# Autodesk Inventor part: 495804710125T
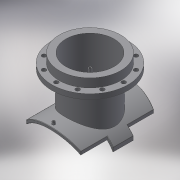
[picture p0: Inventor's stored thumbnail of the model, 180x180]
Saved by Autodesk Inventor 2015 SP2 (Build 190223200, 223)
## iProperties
Created: 2017-10
Part Number: 495804710125T
Material: Generic
Description: PLASSON FLANGED BRANCH SADDLE 315-400X250
Document SubType Name: Modeling
Designer: KIM
Density: 1 g/cm^3
Appearance: Default
Author: KIM
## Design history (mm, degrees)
derived "495904.ipt"
feature "Solid1::495904.ipt"
feature "Solid2::495904.ipt"
tag "TaggingFeature1"
body "Solid1"
other parameters: "d1" = 15, "d2" = 283.5, "d4" = 0, "d5" = 315, "d6" = 105, "d7" = 0, "d11" = 2, "d12" = 225.6, "d13" = 14, "d14" = 189, "d16" = 5 deg, "d18" = 4, "d19" = 14, "d20" = 0, "d21" = 3, "d22" = 0, "d36" = 189, "d38" = 0, "d39" = 2, "d40" = 225, "d43" = 395, "d46" = 256, "d47" = 16, "d48" = 10.4, "d49" = 157.5, "d51" = 408, "d53" = 0, "d54" = 22, "d55" = 175, "d57" = 0, "d59" = 360 deg, "d61" = 26, "d63" = 0, "B_" = 315, "H_" = 225, "x_" = 15, "D_" = 16, "D_1" = 395, "t_" = 26, "s_" = 22
